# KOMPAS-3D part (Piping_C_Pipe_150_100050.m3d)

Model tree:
1. Plane XY
2. Plane ZX
3. Plane ZY
4. X Axis
5. Y Axis
6. Z Axis
7. Origin
8. Path  (labels: Задвижка Dy 150; Труба Dy 150; Тройник Dy 150)
9. Plane of section
10. Section of pipe
11. Pipe
     Толщина стенки 1 = 1

Referenced files in C:\Program Files\ASCON\KOMPAS-3D V10\Libs\Piping\Models\Tanks\: Tanks.a3d
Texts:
  Pipe Dn 150
  Steel ASTM A295
  Three Point Plane
  Plane at Angle
  Line and Point Plane
  Axis through Two Vertices
  Axis of Feature
  Axis of Conical Surface
  Axis through Edge
  Приклеить элемент выдавливания
  Приклеить элемент вращения
  Приклеить кинематический элемент
  Приклеить элемент по сечениям
  Trim by Surface
  Trim by Sketch
  Feature with No History
  Intersection Axis of Two Planes
  Two Line Plane
  Line and Face Plane
  Bend by line
  Hole in sheet body
  Cut in sheet body
  Point in CM
  Linear Dimension from Line to Point
  Surface Finish Symbol
  Geometric Tolerance Symbol
  Текст на чертеже
  Линия-выноска #1
  Линия-выноска #2
  Линия-выноска #3
  Отклонения формы и база
  Марка координационной оси
  Марка/позиционное обозначение с линией-выноской
  Марка/позиционное обозначение на линии
  Марка/позиционное обозначение без линии-выноски
  Задвижка Dy 150
  Труба Dy 150
  Тройник Dy 150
